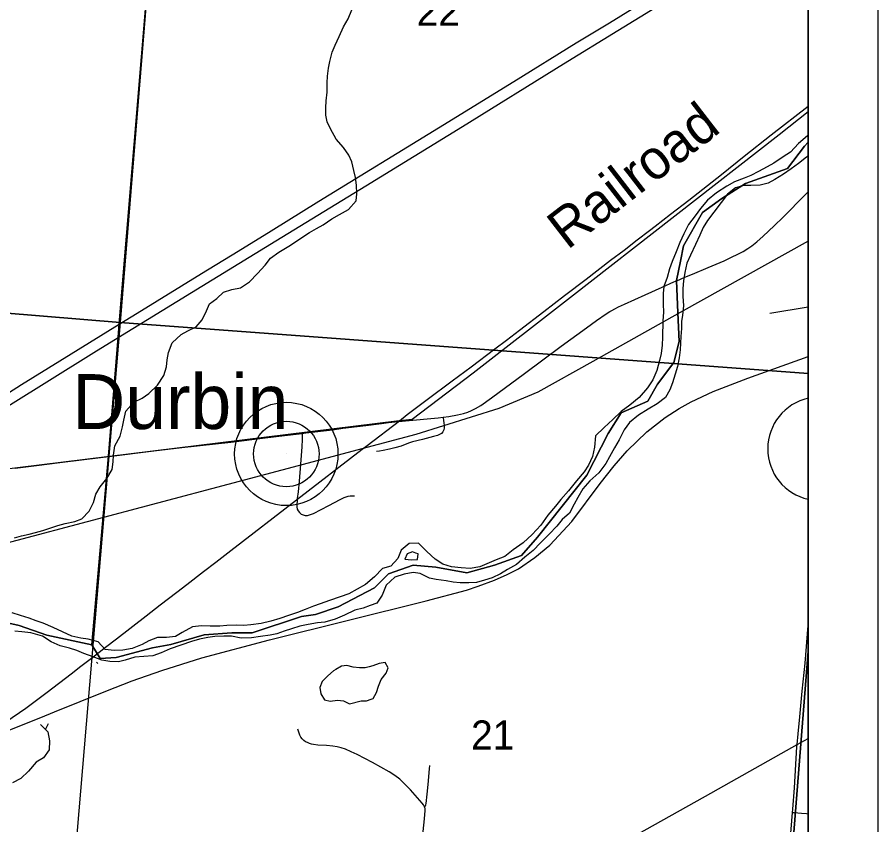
# Model space of a CAD drawing. Extents: x 831 to 1552, y 430 to 870.
# Drawn here: x 1363.98 to 1388.77, y 704.66 to 727.92 of the extents above; entities that cross this region are included whole.
import ezdxf

# ---------------------------------------------------------------- set-up
doc = ezdxf.new("R2010")
doc.units = 0
for name, color, linetype in [('GM_X_Corporation', 7, 'Continuous'), ('GM_X_County_Road', 7, 'Continuous'), ('GM_X_Major_River', 7, 'Continuous'), ('GM_X_Minor_Lake', 7, 'Continuous'), ('GM_X_Minor_River', 7, 'Continuous'), ('GM_X_Rail_Line', 7, 'Continuous'), ('GM_X_Rail_Line_Text', 7, 'Continuous'), ('GM_X_Section_Text', 7, 'Continuous'), ('GM_X_State_Route', 7, 'Continuous'), ('GM_X_Township_Road', 7, 'Continuous'), ('GM_X_Unincorporated', 7, 'Continuous'), ('GM_X_Unincorporated_Location', 7, 'Continuous'), ('GM_X_Unincorporated_Text', 7, 'Continuous'), ('SH_Data', 7, 'Continuous')]:
    doc.layers.add(name, color=color, linetype=linetype)

msp = doc.modelspace()

# ---------------------------------------------------------------- linework, layer by layer
at = {"layer": 'GM_X_Corporation'}
for points in [[(1367.995, 731.953), (1366.919, 719.088), (1366.888, 718.702), (1366.617, 715.279), (1366.13, 709.843), (1366.37, 709.447), (1366.834, 709.478), (1367.884, 709.756), (1368.408, 709.849), (1369.366, 710.127), (1370.168, 710.189), (1370.755, 710.189), (1372.175, 710.652), (1372.577, 710.714), (1373.225, 710.93), (1374.275, 711.486), (1374.676, 711.887), (1375.386, 712.134), (1376.035, 712.073), (1376.93, 711.918), (1377.733, 712.135), (1378.505, 712.412), (1378.968, 712.937), (1380.388, 714.728), (1381.006, 715.932), (1381.377, 716.519), (1382.148, 716.858), (1382.426, 717.352), (1382.895, 717.973), (1383.043, 718.578), (1383.011, 719.409), (1382.971, 720.339), (1383.088, 720.891), (1383.167, 721.335), (1383.723, 722.293), (1384.279, 722.694), (1384.958, 723.127), (1386.162, 723.559), (1386.656, 724.207), (1386.766, 724.317), (1386.766, 758.465)], [(1363.434, 710.53), (1364.039, 710.393), (1364.837, 710.118), (1366.13, 709.843), (1366.617, 715.279), (1366.888, 718.702), (1366.919, 719.088), (1367.995, 731.953)], [(1386.766, 650.938), (1386.766, 724.317), (1386.656, 724.207), (1386.162, 723.559), (1384.958, 723.127), (1384.279, 722.694), (1383.723, 722.293), (1383.167, 721.335), (1383.088, 720.891), (1382.971, 720.339), (1383.011, 719.409), (1383.043, 718.578), (1382.895, 717.973), (1382.426, 717.352), (1382.148, 716.858), (1381.377, 716.519), (1381.006, 715.932), (1380.388, 714.728), (1378.968, 712.937), (1378.505, 712.412), (1377.733, 712.135), (1376.93, 711.918), (1376.035, 712.073), (1375.386, 712.134), (1374.676, 711.887), (1374.275, 711.486), (1373.225, 710.93), (1372.577, 710.714), (1372.175, 710.652), (1370.755, 710.189), (1370.168, 710.189), (1369.366, 710.127), (1368.408, 709.849), (1367.884, 709.756), (1366.834, 709.478), (1366.37, 709.447), (1366.13, 709.843), (1364.837, 710.118), (1364.039, 710.393), (1363.434, 710.53)]]:
    msp.add_lwpolyline(points, dxfattribs=at)
for points in [[(1348.747, 741.721), (1368.637, 739.883), (1366.951, 719.126), (1347.89, 720.702)], [(1386.766, 717.659), (1386.766, 738.222), (1368.637, 739.883), (1366.951, 719.126)], [(1347.89, 720.702), (1366.951, 719.126), (1365.244, 698.931), (1346.049, 700.645)], [(1386.766, 709.654), (1386.766, 717.659), (1366.951, 719.126), (1365.244, 698.931), (1385.781, 697.271)], [(1386.766, 697.192), (1386.766, 709.654), (1385.781, 697.271)]]:
    msp.add_lwpolyline(points, close=True, dxfattribs=at)
at = {"layer": 'GM_X_County_Road'}
msp.add_line((1386.444, 706.965), (1386.766, 707.144), dxfattribs=at)
for points in [[(1382.976, 720.329), (1383.209, 720.427), (1383.435, 720.518), (1383.88, 720.71), (1384.338, 720.904), (1384.552, 721.004), (1384.74, 721.094), (1384.887, 721.175), (1385.028, 721.261), (1385.138, 721.336), (1385.283, 721.446), (1385.469, 721.611), (1385.783, 721.914), (1386.037, 722.163), (1386.251, 722.375), (1386.463, 722.588), (1386.766, 722.892)], [(1376.246, 716.397), (1376.417, 716.419), (1376.66, 716.462), (1376.84, 716.505), (1376.957, 716.544), (1377.071, 716.59), (1377.181, 716.645), (1377.34, 716.739), (1377.644, 716.953), (1378.59, 717.659), (1379.653, 718.448), (1380.377, 718.973), (1380.67, 719.188), (1380.944, 719.378), (1381.049, 719.445), (1381.104, 719.476), (1381.19, 719.523), (1381.3, 719.578), (1381.47, 719.658), (1382.064, 719.923), (1382.56, 720.139), (1382.89, 720.293), (1382.943, 720.315), (1382.976, 720.329)], [(1372.192, 715.93), (1372.295, 715.943), (1373.062, 716.038), (1373.366, 716.079), (1374.022, 716.16), (1374.475, 716.218), (1374.674, 716.241), (1375.166, 716.289), (1376.109, 716.381), (1376.246, 716.397)], [(1366.621, 715.268), (1367.92, 715.428), (1368.722, 715.521), (1370.138, 715.683), (1371.125, 715.801), (1371.679, 715.866), (1372.192, 715.93)], [(1363.922, 714.929), (1364.539, 715.009), (1365.216, 715.093), (1365.832, 715.171), (1366.379, 715.238), (1366.621, 715.268)], [(1378.739, 702.59), (1378.784, 702.616), (1380.13, 703.393), (1381.801, 704.353), (1383.804, 705.482), (1386.134, 706.793), (1386.444, 706.965)]]:
    msp.add_lwpolyline(points, dxfattribs=at)
at = {"layer": 'GM_X_Major_River'}
for points in [[(1386.766, 724.531), (1386.738, 724.504), (1386.482, 724.281), (1386.248, 724.035), (1386.04, 723.895), (1385.777, 723.718), (1385.584, 723.608), (1385.33, 723.477), (1385.115, 723.36), (1384.923, 723.288), (1384.639, 723.18), (1384.416, 723.056), (1384.122, 722.864), (1383.867, 722.649), (1383.663, 722.41), (1383.506, 722.201), (1383.318, 721.946), (1383.183, 721.683), (1383.063, 721.427), (1382.958, 721.163), (1382.845, 720.884), (1382.772, 720.672), (1382.698, 720.423), (1382.608, 720.159), (1382.589, 719.961), (1382.59, 719.657), (1382.592, 719.421), (1382.579, 719.17), (1382.568, 718.706), (1382.555, 718.471), (1382.527, 718.236), (1382.484, 718.031), (1382.402, 717.744), (1382.289, 717.473), (1382.132, 717.24), (1381.89, 716.964), (1381.626, 716.742), (1381.379, 716.564), (1381.138, 716.334), (1380.889, 716.104), (1380.64, 715.858), (1380.61, 715.539), (1380.551, 715.267), (1380.431, 715.018), (1380.313, 714.823), (1380.094, 714.569), (1379.859, 714.278), (1379.641, 714.031), (1379.484, 713.837), (1379.265, 713.576), (1379.061, 713.291), (1378.812, 713.015), (1378.555, 712.777), (1378.269, 712.578), (1378.022, 712.386), (1377.776, 712.285), (1377.507, 712.169), (1377.308, 712.09), (1377.025, 712.042), (1376.767, 712.056), (1376.494, 712.084), (1376.244, 712.166), (1376.019, 712.308), (1375.779, 712.528), (1375.538, 712.771), (1375.273, 712.762), (1375.044, 712.565), (1374.947, 712.324), (1374.745, 712.108), (1374.507, 712.037), (1374.274, 711.798), (1374.018, 711.576), (1373.533, 711.313), (1373.287, 711.219), (1372.981, 711.119), (1372.712, 711.019), (1372.52, 710.954), (1372.275, 710.861), (1372.052, 710.774), (1371.799, 710.689), (1371.547, 710.603), (1371.286, 710.517), (1371.011, 710.455), (1370.713, 710.416), (1370.515, 710.397), (1370.295, 710.402), (1370.021, 710.393), (1369.823, 710.382), (1369.541, 710.381), (1369.29, 710.386), (1369.031, 710.354), (1368.738, 710.2)], [(1386.766, 723.934), (1386.716, 723.888), (1386.484, 723.703), (1386.268, 723.548), (1386.051, 723.4), (1385.804, 723.246), (1385.612, 723.144), (1385.382, 723.08), (1385.108, 723.071), (1384.911, 723.075), (1384.673, 723.004), (1384.441, 722.819), (1384.253, 722.58), (1384.049, 722.303), (1383.861, 722.063), (1383.742, 721.861), (1383.638, 721.642), (1383.518, 721.371), (1383.374, 721.07), (1383.27, 720.836), (1383.211, 720.571), (1383.175, 720.329), (1383.155, 720.101), (1383.15, 719.88), (1383.174, 719.606), (1383.138, 719.341), (1383.118, 719.151), (1383.114, 718.953), (1383.093, 718.718), (1383.081, 718.528), (1383.077, 718.338), (1383.049, 718.11), (1382.998, 717.86), (1382.932, 717.634), (1382.858, 717.392), (1382.777, 717.188), (1382.65, 716.963), (1382.411, 716.785), (1382.156, 716.631), (1381.878, 716.455), (1381.615, 716.247), (1381.458, 716.03), (1381.315, 715.744), (1381.188, 715.519), (1381.045, 715.256), (1380.934, 715.06), (1380.731, 714.799), (1380.474, 714.561), (1380.271, 714.337), (1380.129, 714.089), (1380.026, 713.894), (1379.89, 713.63), (1379.681, 713.452), (1379.524, 713.258), (1379.299, 713.027), (1379.057, 712.774), (1378.839, 712.558), (1378.607, 712.365), (1378.366, 712.15), (1378.104, 712.011), (1377.904, 711.886), (1377.658, 711.77), (1377.436, 711.699), (1377.214, 711.635), (1376.985, 711.625), (1376.742, 711.63), (1376.537, 711.65), (1376.34, 711.685), (1376.052, 711.721), (1375.855, 711.756), (1375.592, 711.891), (1375.387, 711.919), (1375.127, 711.879), (1374.859, 711.793), (1374.61, 711.555), (1374.498, 711.269), (1374.34, 711.044), (1374.149, 710.972), (1373.942, 710.9), (1373.704, 710.837), (1373.412, 710.699), (1373.136, 710.576), (1372.845, 710.491), (1372.631, 710.473), (1372.364, 710.425), (1372.127, 710.377), (1371.882, 710.299), (1371.675, 710.235), (1371.46, 710.156), (1371.269, 710.115), (1370.987, 710.083)], [(1375.467, 712.483), (1375.371, 712.521), (1375.211, 712.462), (1375.148, 712.304)], [(1375.148, 712.304), (1375.338, 712.286), (1375.513, 712.299), (1375.53, 712.459), (1375.467, 712.483)], [(1368.738, 710.2), (1368.546, 710.083), (1368.279, 710.051), (1368.028, 710.049), (1367.774, 709.955), (1367.582, 709.845), (1367.29, 709.738), (1367.023, 709.69), (1366.772, 709.681), (1366.522, 709.709), (1366.313, 709.926), (1366.026, 710.001), (1365.814, 710.029), (1365.556, 710.088), (1365.285, 710.215), (1365.022, 710.343), (1364.736, 710.463), (1364.532, 710.536), (1364.328, 710.609), (1364.079, 710.683), (1363.837, 710.764)], [(1370.987, 710.083), (1370.728, 710.043), (1370.431, 710.034), (1370.158, 710.086), (1369.938, 710.091), (1369.679, 710.081), (1369.473, 710.055), (1369.236, 710.007), (1368.999, 709.936), (1368.385, 709.721), (1368.132, 709.613), (1367.894, 709.519), (1367.627, 709.502), (1367.376, 709.485), (1367.093, 709.4), (1366.901, 709.351), (1366.651, 709.364), (1366.423, 709.399), (1366.167, 709.496), (1365.903, 709.586), (1365.699, 709.674), (1365.488, 709.747), (1365.223, 709.813), (1364.967, 709.926), (1364.712, 710.091), (1364.38, 710.182), (1364.114, 710.218), (1363.917, 710.23)]]:
    msp.add_lwpolyline(points, dxfattribs=at)
at = {"layer": 'GM_X_Minor_Lake'}
for points in [[(1374.181, 708.279), (1374.233, 708.297), (1374.334, 708.471), (1374.389, 708.645), (1374.467, 708.841), (1374.606, 709.022), (1374.669, 709.173), (1374.58, 709.333), (1374.405, 709.298), (1374.229, 709.231), (1374.115, 709.202), (1374.001, 709.181), (1373.841, 709.175), (1373.659, 709.2), (1373.477, 709.24), (1373.325, 709.227), (1373.157, 709.13)], [(1373.157, 709.13), (1373.095, 709.093), (1372.934, 708.943), (1372.765, 708.785), (1372.702, 708.611), (1372.73, 708.429), (1372.835, 708.26), (1373.001, 708.22), (1373.207, 708.248), (1373.381, 708.224), (1373.555, 708.138), (1373.89, 708.225), (1374.042, 708.231), (1374.181, 708.279)]]:
    msp.add_lwpolyline(points, dxfattribs=at)
at = {"layer": 'GM_X_Minor_River'}
for points in [[(1363.905, 712.922), (1364.111, 712.98), (1364.324, 713.031), (1364.514, 713.074), (1364.72, 713.132), (1364.949, 713.213), (1365.155, 713.279), (1365.369, 713.337), (1365.643, 713.395), (1365.841, 713.468), (1366.057, 713.694), (1366.181, 713.943), (1366.253, 714.177), (1366.369, 714.396), (1366.562, 714.63), (1366.717, 714.893), (1366.743, 715.113), (1366.76, 715.303), (1366.794, 715.576), (1366.949, 715.848), (1367.013, 716.12), (1367.054, 716.317), (1367.11, 716.567), (1367.341, 716.83), (1367.586, 716.949), (1367.777, 717.076), (1368.023, 717.316), (1368.209, 717.602), (1368.281, 717.852), (1368.306, 718.049), (1368.339, 718.262), (1368.449, 718.541), (1368.702, 718.781), (1368.901, 718.885), (1369.138, 719.004), (1369.315, 719.207), (1369.433, 719.464), (1369.526, 719.66), (1369.733, 719.817), (1369.925, 719.997), (1370.169, 720.078), (1370.413, 720.128), (1370.674, 720.3), (1370.904, 720.54), (1371.128, 720.781), (1371.275, 720.976), (1371.52, 721.156), (1371.803, 721.327), (1372.4, 721.715), (1372.599, 721.834), (1372.791, 721.938), (1373.043, 722.11), (1373.265, 722.236), (1373.525, 722.378), (1373.741, 722.633), (1373.767, 722.831), (1373.754, 723.081), (1373.727, 723.302), (1373.676, 723.5), (1373.618, 723.751), (1373.53, 723.942), (1373.38, 724.164), (1373.171, 724.41), (1373.007, 724.708), (1372.911, 724.907), (1372.868, 725.097), (1372.87, 725.31), (1372.88, 725.507), (1372.906, 725.765), (1372.91, 726.031), (1372.92, 726.221), (1372.953, 726.456), (1372.986, 726.645), (1373.05, 726.91), (1373.136, 727.114), (1373.253, 727.364), (1373.378, 727.643), (1373.518, 727.87), (1373.62, 728.134)], [(1366.265, 709.345), (1366.302, 709.302)], [(1364.651, 707.544), (1364.869, 707.336), (1364.919, 707.078), (1364.908, 706.812), (1364.738, 706.586), (1364.532, 706.46), (1364.308, 706.204), (1364.085, 705.994), (1363.848, 705.868)], [(1364.797, 707.405), (1364.887, 707.572)]]:
    msp.add_lwpolyline(points, dxfattribs=at)
at = {"layer": 'GM_X_Rail_Line'}
msp.add_line((1386.766, 714.034), (1386.766, 716.942), dxfattribs=at)
for points in [[(1363.656, 707.626), (1364.236, 708.019), (1364.845, 708.472), (1365.539, 709.009), (1365.814, 709.222), (1366.159, 709.489), (1366.526, 709.77), (1366.839, 710.015), (1367.694, 710.673), (1368.103, 710.989), (1368.582, 711.359), (1368.865, 711.575), (1369.352, 711.954), (1369.7, 712.219), (1370.139, 712.558), (1373.914, 715.472), (1374.061, 715.585), (1374.989, 716.295), (1375.214, 716.474), (1375.793, 716.908), (1376.506, 717.444), (1377.054, 717.849), (1377.739, 718.365), (1378.07, 718.616), (1378.452, 718.907), (1379.149, 719.442), (1379.747, 719.904), (1380.365, 720.371), (1381.073, 720.918), (1381.46, 721.214), (1381.837, 721.507), (1382.193, 721.78), (1382.353, 721.905), (1382.794, 722.243), (1383.322, 722.65), (1384.263, 723.392), (1384.922, 723.916), (1385.696, 724.533), (1386.766, 725.362)], [(1374.985, 716.306), (1375.355, 716.338), (1377.116, 717.677), (1379.915, 719.855), (1385.923, 724.544), (1386.766, 725.201)], [(1386.766, 721.465), (1383.073, 719.41), (1380.56, 718.007), (1378.973, 717.119), (1377.858, 716.645), (1375.459, 715.895), (1373.909, 715.483)], [(1363.725, 707.372), (1364.669, 707.744), (1365.061, 707.909), (1366.541, 708.51), (1367.296, 708.806), (1368.148, 709.101), (1369.297, 709.464), (1371.253, 709.985), (1375.759, 711.108), (1376.922, 711.416), (1377.257, 711.528), (1377.724, 711.702), (1378.093, 711.865), (1378.416, 712.027), (1378.886, 712.352), (1379.319, 712.709), (1379.96, 713.395), (1380.776, 714.483), (1381.172, 714.992), (1381.549, 715.429), (1382.116, 715.975), (1382.647, 716.391), (1383.045, 716.649), (1383.39, 716.843), (1384.025, 717.136), (1385.028, 717.523), (1386.766, 718.15)], [(1357.73, 710.582), (1358.866, 711.407), (1363.361, 714.868), (1374.985, 716.306)], [(1373.909, 715.483), (1372.078, 714.996), (1361.934, 712.311), (1359.948, 711.564), (1359.186, 711.251), (1357.73, 710.582)]]:
    msp.add_lwpolyline(points, dxfattribs=at)
msp.add_arc((1387.084, 715.488), 1.488, 102.34, 257.66, dxfattribs=at)
at = {"layer": 'GM_X_State_Route'}
for points in [[(1357.165, 712.965), (1357.324, 713.064), (1358.466, 713.785), (1359.485, 714.418), (1360.53, 715.085), (1361.949, 715.98), (1363.001, 716.643), (1364.105, 717.338), (1365.214, 718.025), (1366.924, 719.077), (1367.436, 719.392), (1369.287, 720.533), (1370.346, 721.183), (1371.298, 721.77), (1372.674, 722.617), (1376.115, 724.732), (1378.283, 726.071), (1380.083, 727.178), (1381.036, 727.763), (1382.148, 728.446), (1383.542, 729.306)], [(1357.698, 712.915), (1358.653, 713.517), (1361.41, 715.266), (1363.714, 716.719), (1366.193, 718.261), (1366.893, 718.692), (1369.002, 719.989), (1371.428, 721.477), (1374.021, 723.067), (1376.806, 724.775), (1379.716, 726.578), (1381.284, 727.542), (1383.511, 728.914)]]:
    msp.add_lwpolyline(points, dxfattribs=at)
at = {"layer": 'GM_X_Township_Road'}
msp.add_line((1386.766, 719.571), (1385.661, 719.386), dxfattribs=at)
for points in [[(1376.246, 716.397), (1376.248, 716.375), (1376.256, 716.305), (1376.268, 716.237), (1376.278, 716.155), (1376.278, 716.096), (1376.267, 716.035), (1376.239, 715.98), (1376.199, 715.932), (1376.149, 715.897), (1376.092, 715.872), (1375.969, 715.842), (1375.655, 715.76), (1375.371, 715.684), (1375.253, 715.645), (1375.043, 715.568), (1374.862, 715.512), (1374.702, 715.474), (1374.525, 715.436), (1374.418, 715.416), (1374.327, 715.406)], [(1372.192, 715.93), (1372.192, 715.882), (1372.192, 715.757), (1372.177, 715.542), (1372.142, 715.048), (1372.1, 714.553), (1372.071, 714.243), (1372.051, 714.059), (1372.042, 713.997), (1372.033, 713.873), (1372.037, 713.811), (1372.051, 713.751), (1372.079, 713.696), (1372.118, 713.648), (1372.165, 713.609), (1372.219, 713.583), (1372.279, 713.567), (1372.341, 713.568), (1372.401, 713.581), (1372.517, 713.625), (1372.958, 713.855), (1373.287, 714.029), (1373.398, 714.083), (1373.455, 714.105), (1373.515, 714.122), (1373.574, 714.132), (1373.634, 714.136), (1373.694, 714.131)], [(1386.444, 706.965), (1386.473, 707.272), (1386.519, 707.767), (1386.593, 708.509), (1386.672, 709.312), (1386.766, 710.401)], [(1375.715, 705.172), (1375.698, 705.211), (1375.684, 705.234), (1375.645, 705.283), (1375.307, 705.66), (1375.137, 705.84), (1375.001, 705.966), (1374.854, 706.08), (1374.698, 706.18), (1374.211, 706.449), (1373.772, 706.68), (1373.605, 706.762), (1373.434, 706.833), (1373.317, 706.872), (1373.197, 706.902), (1373.074, 706.922), (1372.889, 706.938), (1372.642, 706.954), (1372.519, 706.97), (1372.459, 706.983), (1372.4, 707.001), (1372.342, 707.024), (1372.286, 707.05), (1372.235, 707.086), (1372.191, 707.129), (1372.154, 707.178), (1372.126, 707.234), (1372.063, 707.408)], [(1386.309, 705.011), (1386.317, 705.104), (1386.364, 705.724), (1386.438, 706.901), (1386.444, 706.965)], [(1375.715, 705.172), (1375.726, 705.181), (1375.743, 705.201), (1375.752, 705.232), (1375.76, 705.269), (1375.794, 705.542), (1375.817, 705.82), (1375.837, 706.034), (1375.847, 706.158), (1375.857, 706.272), (1375.866, 706.361)], [(1375.657, 704.276), (1375.712, 704.83), (1375.726, 704.953), (1375.733, 705.056), (1375.734, 705.097), (1375.732, 705.124), (1375.726, 705.148), (1375.715, 705.172)], [(1386.16, 703.143), (1386.205, 703.68), (1386.246, 704.176), (1386.309, 705.011)], [(1386.309, 705.011), (1386.356, 705.007), (1386.568, 704.991), (1386.711, 704.979), (1386.766, 704.972)]]:
    msp.add_lwpolyline(points, dxfattribs=at)
at = {"layer": 'GM_X_Unincorporated'}
for radius in [1.488, 0.943]:
    msp.add_circle((1371.734, 715.339), radius, dxfattribs=at)
at = {"layer": 'GM_X_Unincorporated_Location'}
msp.add_line((1371.734, 715.339), (1371.734, 715.339), dxfattribs=at)
at = {"layer": 'SH_Data'}
for p, q in [((1388.766, 788.938), (1388.766, 648.938)), ((1386.766, 786.938), (1386.766, 650.938))]:
    msp.add_line(p, q, dxfattribs=at)

# ---------------------------------------------------------------- texts
at = {"layer": 'GM_X_Rail_Line_Text'}
msp.add_text('Railroad', height=1.1326, rotation=37.666, dxfattribs=at).set_placement((1379.824, 721.199))
at = {"layer": 'GM_X_Section_Text'}
for s, p in [('22', (1375.487, 727.674)), ('21', (1377.054, 706.824))]:
    msp.add_text(s, height=0.8371, rotation=0, dxfattribs=at).set_placement(p)
at = {"layer": 'GM_X_Unincorporated_Text'}
msp.add_text('Durbin', height=1.5795, rotation=0, dxfattribs=at).set_placement((1365.571, 716.058))

doc.saveas('drawing.dxf')
